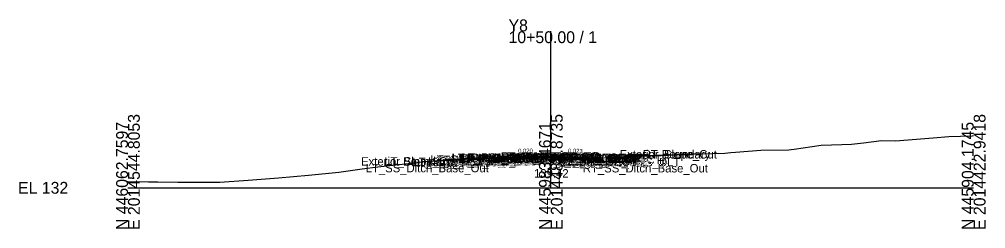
# Model space of a CAD drawing. Extents: x -26 to 1403, y -10 to 8043.
# Drawn here: x -25.7 to 202.8, y 990.3 to 1039.9 of the extents above; entities that cross this region are included whole.
import ezdxf

# ---------------------------------------------------------------- set-up
doc = ezdxf.new("R2010")
doc.units = 0
for name, color, linetype in [('Default', 7, 'Continuous'), ('Exist CMT Pavement', 7, 'Continuous'), ('Exist Cross Section Cell', 7, 'Continuous'), ('Exist XS Center Line Elevation Label', 7, 'Continuous'), ('Exist XS Ground Line', 7, 'Continuous'), ('Prop CMT Pvmt Course 1', 7, 'Continuous'), ('Prop CMT Pvmt Course 1 Wedge', 7, 'Continuous'), ('Prop CMT Pvmt Course 2', 7, 'Continuous'), ('Prop CMT Pvmt Course 2 Wedge', 7, 'Continuous'), ('Prop CMT Pvmt Course 3', 7, 'Continuous'), ('Prop CMT Pvmt Course 3 Wedge', 7, 'Continuous'), ('Prop CMT Pvmt Surface', 7, 'Continuous'), ('Prop CMT Pvmt Surface Shoulder', 7, 'Continuous'), ('Prop CMT Pvmt Wedge Surface 1', 7, 'Continuous'), ('Prop CMT Pvmt Wedge Surface 2', 7, 'Continuous'), ('Prop CMT Pvmt Wedge Surface 3', 7, 'Continuous'), ('Prop CMT Shld Paved Course 1', 7, 'Continuous'), ('Prop CMT Shld Paved Course 2', 7, 'Continuous'), ('Prop CMT Shld Paved Course 3', 7, 'Continuous'), ('Prop CMT Slope Grass', 7, 'Continuous'), ('Prop CMT Subgrade Earthwork', 7, 'Continuous'), ('Prop XS Earthwork Shape', 7, 'Continuous'), ('Prop XS SE Text', 7, 'Continuous'), ('Scratch_Level_0', 7, 'Continuous')]:
    doc.layers.add(name, color=color, linetype=linetype)

msp = doc.modelspace()

# ---------------------------------------------------------------- linework, layer by layer
at = {"layer": 'Exist CMT Pavement'}
msp.add_lwpolyline([(89.13, 1007.08), (89.23, 1007.08), (100, 1007.42), (100.51, 1007.44), (109.41, 1007.09), (110.54, 1007.05)], dxfattribs=at)
at = {"layer": 'Exist Cross Section Cell'}
for p, q in [((100, 1000), (100, 1037.08)), ((0, 1000), (100, 1000)), ((100, 1000), (200, 1000))]:
    msp.add_line(p, q, dxfattribs=at)
at = {"layer": 'Exist XS Ground Line'}
msp.add_lwpolyline([(0, 1001.5), (4.89, 1001.41), (7.04, 1001.39), (11.82, 1001.37), (21.75, 1001.32), (28.45, 1001.84), (35.57, 1002.38), (42.73, 1003), (49.83, 1003.74), (55.35, 1004.47), (59.07, 1004.95), (68.43, 1005.99), (68.88, 1006.04), (75.48, 1006.69), (77.32, 1006.8), (82.41, 1007.07), (83.49, 1007.1), (84.25, 1007.09), (88.31, 1007.06), (88.7, 1007.06), (89.23, 1007.08), (100, 1007.42), (100.51, 1007.44), (109.41, 1007.09), (110.8, 1007.04), (113.2, 1007.19), (121.16, 1007.67), (124.73, 1007.76), (128.29, 1007.83), (131.02, 1007.9), (135.42, 1008.05), (141.14, 1008.23), (142.55, 1008.36), (143.64, 1008.42), (149.69, 1008.9), (156.25, 1009.02), (156.82, 1009.06), (157.56, 1009.13), (163.95, 1010.11), (168.86, 1010.22), (171.08, 1010.37), (173.97, 1010.66), (178.22, 1011.23), (181.48, 1011.09), (190.39, 1011.85), (194.09, 1012.13), (199.61, 1012.35), (200, 1012.36)], dxfattribs=at)
at = {"layer": 'Prop CMT Pvmt Course 1'}
for points in [[(100, 1007.39), (88.13, 1007.15)], [(88.13, 1007.15), (88.13, 1006.9)], [(88.13, 1006.9), (89.13, 1006.92)], [(89.13, 1007.05), (100, 1007.26)], [(89.13, 1006.92), (89.13, 1007.05)], [(100, 1007.14), (100, 1007.39)], [(100, 1007.39), (111.54, 1007.12)], [(100, 1007.14), (100, 1007.39)], [(100, 1007.26), (100, 1007.14), (100, 1007.14)], [(110.54, 1007.02), (100, 1007.26)], [(100, 1007.26), (100, 1007.14), (100, 1007.14)], [(110.54, 1006.89), (110.54, 1007.02)], [(111.54, 1006.87), (110.54, 1006.89)], [(111.54, 1007.12), (111.54, 1006.87)]]:
    msp.add_lwpolyline(points, dxfattribs=at)
at = {"layer": 'Prop CMT Pvmt Course 1 Wedge'}
for points in [[(100, 1007.26), (89.13, 1007.05)], [(100, 1007.26), (110.54, 1007.02)]]:
    msp.add_lwpolyline(points, dxfattribs=at)
at = {"layer": 'Prop CMT Pvmt Course 2'}
for points in [[(89.13, 1006.92), (88.13, 1006.9)], [(88.13, 1006.9), (88.13, 1006.65)], [(88.13, 1006.65), (89.13, 1006.67)], [(89.13, 1006.67), (89.13, 1006.92)], [(110.54, 1006.64), (110.54, 1006.89)], [(110.54, 1006.89), (111.54, 1006.87)], [(111.54, 1006.62), (110.54, 1006.64)], [(111.54, 1006.87), (111.54, 1006.62)]]:
    msp.add_lwpolyline(points, dxfattribs=at)
at = {"layer": 'Prop CMT Pvmt Course 2 Wedge'}
for points in [[(100, 1007.14), (89.13, 1006.92)], [(100, 1007.14), (110.54, 1006.89)]]:
    msp.add_lwpolyline(points, dxfattribs=at)
at = {"layer": 'Prop CMT Pvmt Course 3'}
for points in [[(89.13, 1006.67), (88.13, 1006.65)], [(88.13, 1006.65), (88.13, 1006.28)], [(88.13, 1006.28), (89.13, 1006.3)], [(89.13, 1006.3), (89.13, 1006.67)], [(110.54, 1006.64), (111.54, 1006.62)], [(110.54, 1006.27), (110.54, 1006.64)], [(111.54, 1006.25), (110.54, 1006.27)], [(111.54, 1006.62), (111.54, 1006.25)]]:
    msp.add_lwpolyline(points, dxfattribs=at)
at = {"layer": 'Prop CMT Pvmt Course 3 Wedge'}
for points in [[(100, 1006.89), (89.13, 1006.67)], [(100, 1006.89), (110.54, 1006.64)]]:
    msp.add_lwpolyline(points, dxfattribs=at)
at = {"layer": 'Prop CMT Pvmt Surface'}
for points in [[(100, 1007.39), (88.13, 1007.15)], [(100, 1007.39), (111.54, 1007.12)]]:
    msp.add_lwpolyline(points, dxfattribs=at)
at = {"layer": 'Prop CMT Pvmt Surface Shoulder'}
for points in [[(88.13, 1007.15), (88.13, 1007.15)], [(111.54, 1007.12), (111.54, 1007.12)]]:
    msp.add_lwpolyline(points, dxfattribs=at)
at = {"layer": 'Prop CMT Pvmt Wedge Surface 1'}
for points in [[(88.13, 1006.9), (88.13, 1007.15)], [(89.13, 1006.92), (88.13, 1006.9)], [(100, 1007.26), (89.13, 1007.05)], [(89.13, 1007.05), (89.13, 1006.92)], [(100, 1007.26), (110.54, 1007.02)], [(110.54, 1007.02), (110.54, 1006.89)], [(110.54, 1006.89), (111.54, 1006.87)], [(111.54, 1006.87), (111.54, 1007.12)]]:
    msp.add_lwpolyline(points, dxfattribs=at)
at = {"layer": 'Prop CMT Pvmt Wedge Surface 2'}
for points in [[(88.13, 1006.9), (88.13, 1007.15)], [(100, 1007.14), (88.13, 1006.9)], [(100, 1007.14), (111.54, 1006.87)], [(111.54, 1006.87), (111.54, 1007.12)]]:
    msp.add_lwpolyline(points, dxfattribs=at)
at = {"layer": 'Prop CMT Pvmt Wedge Surface 3'}
for points in [[(88.13, 1006.65), (88.13, 1007.15)], [(100, 1006.89), (88.13, 1006.65)], [(100, 1006.89), (111.54, 1006.62)], [(111.54, 1006.62), (111.54, 1007.12)]]:
    msp.add_lwpolyline(points, dxfattribs=at)
at = {"layer": 'Prop CMT Shld Paved Course 1'}
for points in [[(88.13, 1007.15), (87.87, 1006.9)], [(87.87, 1006.9), (88.13, 1006.9)], [(88.13, 1007.15), (88.13, 1007.15)], [(88.13, 1006.9), (88.13, 1007.15)], [(111.54, 1007.12), (111.54, 1007.12)], [(111.54, 1007.12), (111.8, 1006.87)], [(111.54, 1006.87), (111.54, 1007.12)], [(111.8, 1006.87), (111.54, 1006.87)]]:
    msp.add_lwpolyline(points, dxfattribs=at)
at = {"layer": 'Prop CMT Shld Paved Course 2'}
for points in [[(88.13, 1006.9), (87.87, 1006.9), (87.62, 1006.64)], [(87.62, 1006.64), (88.13, 1006.65)], [(88.13, 1006.65), (88.13, 1006.9)], [(111.54, 1006.87), (111.8, 1006.87), (112.05, 1006.61)], [(111.54, 1006.62), (111.54, 1006.87)], [(112.05, 1006.61), (111.54, 1006.62)]]:
    msp.add_lwpolyline(points, dxfattribs=at)
at = {"layer": 'Prop CMT Shld Paved Course 3'}
for points in [[(86.73, 1006.25), (88.13, 1006.28)], [(88.13, 1007.15), (87.23, 1006.26)], [(88.13, 1006.28), (88.13, 1006.65)], [(111.54, 1006.25), (111.54, 1006.62)], [(111.54, 1006.62), (112.05, 1006.61), (112.44, 1006.23)], [(112.94, 1006.22), (111.54, 1006.25)]]:
    msp.add_lwpolyline(points, dxfattribs=at)
at = {"layer": 'Prop CMT Slope Grass'}
for points in [[(111.54, 1007.12), (135.8, 1008.06)], [(88.13, 1007.15), (82.13, 1006.67), (69.76, 1006.13)]]:
    msp.add_lwpolyline(points, dxfattribs=at)
at = {"layer": 'Prop CMT Subgrade Earthwork'}
for p, q in [((86.73, 1006.25), (82.13, 1006.67)), ((112.94, 1006.22), (120.51, 1007.47))]:
    msp.add_line(p, q, dxfattribs=at)
for points in [[(88.13, 1006.28), (86.73, 1006.25)], [(89.13, 1006.3), (88.13, 1006.28)], [(89.13, 1006.3), (89.13, 1007.08)], [(110.54, 1006.27), (110.54, 1007.05)], [(110.54, 1006.27), (111.54, 1006.25)], [(111.54, 1006.25), (112.94, 1006.22)]]:
    msp.add_lwpolyline(points, dxfattribs=at)
at = {"layer": 'Prop XS Earthwork Shape'}
for points in [[(111.77, 1007.1), (113.2, 1007.19), (121.16, 1007.67), (131.02, 1007.9), (135.8, 1008.06), (120.51, 1007.47), (112.94, 1006.22), (111.54, 1006.25), (110.54, 1006.27), (110.54, 1007.05), (110.8, 1007.04)], [(86.73, 1006.25), (82.13, 1006.67), (69.76, 1006.13), (75.48, 1006.69), (77.32, 1006.8), (82.41, 1007.07), (83.49, 1007.1), (84.25, 1007.09), (87.14, 1007.07), (88.31, 1007.06), (88.7, 1007.06), (89.13, 1007.08), (89.13, 1006.3), (88.13, 1006.28)], [(97.25, 1007.33), (100, 1007.42), (100.51, 1007.44), (104.3, 1007.29), (100, 1007.39)]]:
    msp.add_lwpolyline(points, close=True, dxfattribs=at)

# ---------------------------------------------------------------- texts
at = {"layer": 'Default'}
msp.add_text('-', height=0.0001, dxfattribs=at).set_placement((0, 1000))
at = {"layer": 'Exist Cross Section Cell'}
for s, p in [('Y8', (90, 1037.08)), ('10+50.00 / 1', (90, 1034.28)), ('EL 132', (-26, 998.6))]:
    msp.add_text(s, height=2.8, dxfattribs=at).set_placement(p)
for s, p in [('E 2014544.8053', (2.8, 990)), ('E 2014483.8735', (102.8, 990)), ('E 2014422.9418', (202.8, 990)), ('N 446062.7597', (0, 990)), ('N 445983.4671', (100, 990)), ('N 445904.1745', (200, 990))]:
    msp.add_text(s, height=2.8, rotation=90, dxfattribs=at).set_placement(p)
at = {"layer": 'Exist XS Center Line Elevation Label'}
msp.add_text('139.42', height=2, dxfattribs=at).set_placement((96.03, 1002.42))
at = {"layer": 'Prop XS SE Text'}
for s, rotation, p in [('0.020', 1.1458, (92.29, 1008.24)), ('0.023', 358.6633, (104.07, 1008.29))]:
    msp.add_text(s, height=1, rotation=rotation, dxfattribs=at).set_placement(p)
at = {"layer": 'Scratch_Level_0'}
for s, p in [('LT_Sub Tie Out', (76.47, 1006.08)), ('LT_PV_OEEOP_EG', (76.67, 1006.08)), ('LT_PS2_OEOP', (78.11, 1005.9)), ('LT_PV2_OEOT', (78.3, 1005.9)), ('LT_PV2_OEEOP', (78.43, 1005.92)), ('LT_PV1_OEOT', (78.87, 1006.15)), ('LT_PS1_OEOP', (78.93, 1006.15)), ('LT_PV1_OEEOP', (79, 1006.05)), ('RT_PV_IEEOP_EG', (88.14, 1006.42)), ('LT_PV_IEEOP_EG', (88.19, 1006.42)), ('RT_PV2_IEEOP', (89.91, 1006.14)), ('RT_PV3_IEEOP', (89.91, 1005.89)), ('LT_PV2_IEEOP', (89.95, 1006.14)), ('LT_PV3_IEEOP', (89.95, 1005.89)), ('RT_PV1_IEEOP', (90.47, 1006.26)), ('LT_PV1_IEEOP', (90.52, 1006.26)), ('PV2_PGL', (93.91, 1006.14)), ('PV1_PGL', (94.47, 1006.39)), ('RT_Sub Tie Out', (97.83, 1006.05)), ('RT_PV_OEEOP_EG', (98.04, 1006.05)), ('RT_PV2_OEEOP', (99.8, 1005.89)), ('RT_PV1_OEEOP', (100.37, 1006.02)), ('RT_PV2_OEOT', (101.67, 1005.87)), ('RT_PS2_OEOP', (101.99, 1005.87)), ('RT_PV1_OEOT', (102.24, 1006.12)), ('RT_PS1_OEOP', (102.3, 1006.12)), ('Exterior Boundary', (116.28, 1006.94)), ('RT_Slope_Cut', (121.73, 1006.94)), ('Exterior Boundary', (55.12, 1005.25)), ('LT_SS_Ditch_Base_Out', (56.21, 1003.67)), ('LT_Slope_Cut', (60.61, 1005.25)), ('LT_Sub_OSS_DLT', (67.29, 1005.11)), ('LT_Sub_Trench_Out', (70.94, 1005.25)), ('LT_GS_OS_CTL', (71.5, 1005.67)), ('LT_PS3_Shelf_Out', (73.1, 1005.63)), ('LT_PS3_OEOP', (77.85, 1005.64)), ('LT_Sub_OEOT', (78.21, 1005.28)), ('LT_PV3_OEOT', (78.3, 1005.65)), ('LT_Sub_OEEOP', (78.34, 1005.3)), ('LT_PV3_OEEOP', (78.43, 1005.67)), ('RT_Sub_Trench_Out', (97.09, 1005.22)), ('RT_PS3_Shelf_Out', (98.49, 1005.6)), ('RT_Sub_OEEOP', (99.71, 1005.27)), ('RT_PV3_OEEOP', (99.8, 1005.64)), ('RT_Sub_OEOT', (101.57, 1005.25)), ('RT_PV3_OEOT', (101.67, 1005.62)), ('RT_PS3_OEOP', (102.24, 1005.61)), ('RT_GS_OS_CTL', (106.86, 1005.64)), ('RT_Sub_OSS_DLT', (107.14, 1005.08)), ('RT_SS_Ditch_Base_Out', (107.57, 1003.64))]:
    msp.add_text(s, height=2, dxfattribs=at).set_placement(p)

doc.saveas('drawing.dxf')
